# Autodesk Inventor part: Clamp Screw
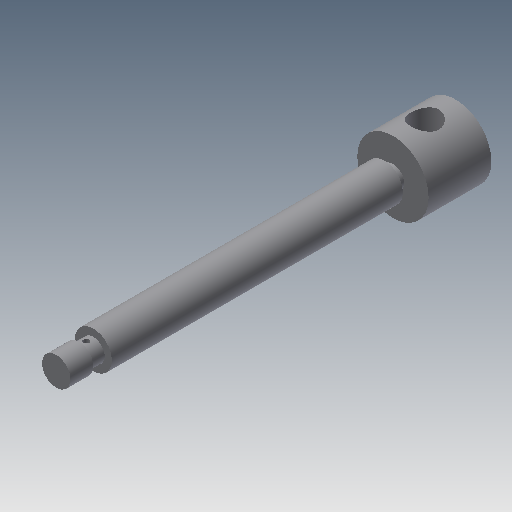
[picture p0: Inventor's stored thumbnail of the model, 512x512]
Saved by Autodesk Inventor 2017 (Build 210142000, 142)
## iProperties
Shininess: 77.0
Length Units: 11269
Angle Units: 11279
Time Units: 11290
Mass Units: 11283
Length Display Precision: 3
Angle Display Precision: 2
Created: 2002-02
Part Number: Clamp Screw
Document SubType Name: Modeling
Designer: ***
Density: 1 g/cm^3
Material: Generic
Mass: 23.4191 g
Surface Area: 81.8482 cm^2
Volume: 23.4191 cm^3
Appearance: Default
Density: 0.0
Volumn: 0.0
Area: 0.0
PropertySet Name: Model Information
Control State: 0
Master: False
Checked Out: False
Author: ***
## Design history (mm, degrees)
sketch "Sketch1"
  geometry: L1 (0, 140)-(5, 140); L2 (5, 140)-(5, 132); L3 (5, 132)-(4, 132); L4 (4, 132)-(4, 127); L5 (4, 127)-(6.5, 127); L6 (6.5, 127)-(6.5, 25); L7 (6.5, 25)-(4, 25); L8 (4, 25)-(4, 22); L9 (4, 22)-(12.5, 22); L10 (12.5, 22)-(12.5, 0); L11 (12.5, 0)-(0, 0); L12 (0, 0)-(0, 140)
  constraints: 24 end point, 10 parallel, 1 horizontal, 1 perpendicular
  dimensions: "d0" = 10 diameter of L2 L12; "d1" = 8 diameter of L4 L12; "d2" = 13 diameter of L6 L12; "d3" = 8 diameter of L7.end L12; "d4" = 25 diameter of L10 L12; "d5" = 3 distance from line of L7.end L9; "d6" = 8 distance of L1.end L2.end; "d7" = 13 vertical distance of L1.end L5.end; "d8" = 22 distance of L9.end L10.end; "d10" = 102 distance of L5.end L6.end
revolve "Revolution1" sketch "Sketch1" stored, may be unused: angle "d11" = 90 deg
sketch "Sketch3"
  geometry: L1 (-12.5, 0)-(12.5, 0) reference; C1 r 5 at (-0.113, 11)
  constraints: 1 centre point
  dimensions: "d13" = 10 diameter of C1; "d14" = 11 distance from line of L1 C1.centre
extrude "Extrusion1" cut sketch "Sketch3" stored distance "d15" = 10; taper "d16" = 0 deg
sketch "Sketch4"
  geometry: L1 (0, 138.841)-(0, 0); L2 (-12.5, 0)-(12.5, 0) reference; L3 (-5, 140)-(5, 140) reference; C1 r 1 at (0, 129.5)
  constraints: 2 end point, 1 centre point, 1 point on line, 1 vertical
  dimensions: "d17" = 2 diameter of C1; "d18" = 10.5 distance from line of L3 C1.centre
extrude "Extrusion2" cut sketch "Sketch4" stored distance "d19" = 10; taper "d20" = 0 deg
body "Solid1"
